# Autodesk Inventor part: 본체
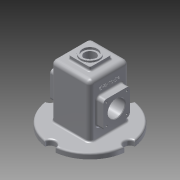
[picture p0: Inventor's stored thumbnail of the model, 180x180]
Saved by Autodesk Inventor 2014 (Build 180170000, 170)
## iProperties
Created: 2018-07
Part Number: 본체
Material: Aluminum 6061
Document SubType Name: Modeling
Designer: kh
Density: 2.71 g/cm^3
Appearance: Aluminum - Flat
Mass: 912.193 g
Surface Area: 1016.11 cm^2
Volume: 336.603 cm^3
Author: kh
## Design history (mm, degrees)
sketch "Sketch1"
  geometry: L1 (-75, 0)-(75, 0); L2 (0, -75)-(0, 75); C1 r 10 at (75, 0); C2 r 10 at (0, 75); C3 r 10 at (-75, 0); C4 r 10 at (0, -75); A1 r 75 centre (0, 0) between (-75, 0) and (75, 0); 1 further point
  constraints: 5 centre point, 5 coincident, 4 end point, 4 point on circle, 1 horizontal, 1 perpendicular
  dimensions: "d0" = 150 diameter of A1; "d2" = 150 distance of L1.start L1.end; "d3" = 150 distance of L2.start L2.end; "d4" = 20 diameter of C1; "d5" = 20 diameter of C2; "d6" = 20 diameter of C3; "d7" = 20 diameter of C4
extrude "Extrusion1" new body sketch "Sketch1" distance "d8" = 10; taper "d9" = 0 deg
extrude "Extrusion2" cut sketch "Sketch1" distance "d10" = 10; taper "d11" = 0 deg
sketch "Sketch2"
  geometry: L1 (-37, -37)-(37, -37); L2 (37, -37)-(37, 37); L3 (37, 37)-(-37, 37); L4 (-37, 37)-(-37, -37); L5 (-37, -37)-(37, 37); L6 (37, -37)-(-37, 37); 1 further point
  constraints: 12 end point, 2 midpoint, 2 parallel, 1 horizontal, 1 perpendicular
  dimensions: "d12" = 74 distance of L3.end L2.end; "d13" = 74 distance of L2.end L1.end
extrude "Extrusion3" join sketch "Sketch2" distance "d14" = 100; taper "d15" = 0 deg
sketch "Sketch3"
  geometry: L1 (-37, -37)-(37, -37) reference; L2 (37, -37)-(37, 37) reference; L3 (37, 37)-(-37, 37) reference; L4 (-37, 37)-(-37, -37) reference; L5 (-20, -20)-(20, -20); L6 (20, -20)-(20, 20); L7 (20, 20)-(-20, 20); L8 (-20, 20)-(-20, -20); L9 (-20, -20)-(20, 20); L10 (20, -20)-(-20, 20); 1 further point
  constraints: 12 end point, 2 midpoint, 2 parallel, 1 horizontal, 1 perpendicular
  dimensions: "d16" = 40 distance of L7.end L6.end; "d17" = 40 distance of L6.end L5.end
extrude "Extrusion4" join sketch "Sketch3" distance "d18" = 7; taper "d19" = 0 deg
sketch "Sketch4"
  geometry: L1 (-20, -20)-(20, -20) reference; L2 (20, -20)-(20, 20) reference; L3 (20, 20)-(-20, 20) reference; L4 (-20, 20)-(-20, -20) reference; C1 r 17.5 at (0, 0); 1 further point
  constraints: 1 centre point, 1 coincident
  dimensions: "d20" = 35 diameter of C1
extrude "Extrusion5" join sketch "Sketch4" distance "d21" = 3; taper "d22" = 0 deg
sketch "Sketch5"
  geometry: L1 (65, 10)-(65, 0) reference; L2 (65, 0)-(-65, 0) reference; L3 (-65, 0)-(-65, 10) reference; L4 (-65, 10)-(-37, 10) reference; L5 (-37, 10)-(-37, 110) reference; L6 (-37, 110)-(-20, 110) reference; L7 (-20, 110)-(-20, 117) reference; L8 (-20, 117)-(-17.5, 117) reference; L9 (-17.5, 117)-(-17.5, 120) reference; L10 (-17.5, 120)-(17.5, 120) reference; L11 (17.5, 120)-(17.5, 117) reference; L12 (17.5, 117)-(20, 117) reference; L13 (20, 117)-(20, 110) reference; L14 (20, 110)-(37, 110) reference; L15 (37, 110)-(37, 10) reference; L16 (37, 10)-(65, 10) reference; L17 (-32, 105)-(32, 105); L18 (32, 105)-(32, 0); L19 (32, 0)-(-32, 0); L20 (-32, 0)-(-32, 105)
  constraints: 8 end point, 2 parallel, 1 horizontal, 1 perpendicular, 1 point on line
  dimensions: "d26" = 64 distance of L18.end L19.end; "d27" = 5 distance between parallel lines of L15 L18; "d29" = 5 distance between parallel lines of L17 L6
extrude "Extrusion6" cut sketch "Sketch5" stored distance "d30" = 64; taper "d31" = 0 deg
sketch "Sketch7"
  geometry: L1 (70, 62)-(20, 62); L2 (20, 62)-(20, 12); L3 (20, 12)-(70, 12); L4 (70, 12)-(70, 62); L5 (70, 37)-(20, 37); L6 (45, 12)-(45, 62); 2 further points
  constraints: 12 end point, 5 midpoint, 2 parallel, 1 horizontal, 1 horizontal alignment, 1 perpendicular
  dimensions: "d33" = 50 distance of L2.end L3.end; "d34" = 50 distance of L1.end L2.end; "d35" = 55 distance from line of point (-10, 37) L6
extrude "Extrusion7" join sketch "Sketch7" distance "d36" = 13; taper "d37" = 0 deg
mirror "Mirror1"
sketch "Sketch8"
  geometry: L1 (65, 10)-(65, 0) reference; L2 (65, 0)-(32, 0) reference; L3 (32, 0)-(32, 105) reference; L4 (32, 105)-(-32, 105) reference; L5 (-32, 105)-(-32, 0) reference; L6 (-32, 0)-(-65, 0) reference; L7 (-65, 0)-(-65, 10) reference; L8 (-65, 10)-(-37, 10) reference; L9 (-37, 10)-(-37, 30) reference; L10 (-37, 30)-(-50, 30) reference; L11 (-50, 30)-(-50, 80) reference; L12 (-50, 80)-(-37, 80) reference; L13 (-37, 80)-(-37, 110) reference; L14 (-37, 110)-(-20, 110) reference; L15 (-20, 110)-(-20, 117) reference; L16 (-20, 117)-(-17.5, 117) reference; L17 (-17.5, 117)-(-17.5, 120) reference; L18 (-17.5, 120)-(17.5, 120) reference; L19 (17.5, 120)-(17.5, 117) reference; L20 (17.5, 117)-(20, 117) reference; L21 (20, 117)-(20, 110) reference; L22 (20, 110)-(37, 110) reference; L23 (37, 110)-(37, 80) reference; L24 (37, 80)-(50, 80) reference; L25 (50, 80)-(50, 30) reference; L26 (50, 30)-(37, 30) reference; L27 (37, 30)-(37, 10) reference; L28 (37, 10)-(65, 10) reference; L29 (-32, 55)-(32, 55); L30 (-32, 30)-(-25, 32.548); L31 (-25, 32.548)-(-25, 55); L32 (-32, 30)-(-32, 55); 1 further point
  constraints: 8 end point, 4 point on line, 2 perpendicular, 1 collinear
  dimensions: "d38" = 55 vertical distance of point (0, 0) L29.end; "d39" = 7 distance between parallel lines of L32 L31; "d40" = 110 deg angle of L5 L30; "d41" = 50 diameter of L30.start L29
revolve "Revolution1" sketch "Sketch8" stored, may be unused: angle "d42" = 90 deg
mirror "Mirror2"
sketch "Sketch9"
  geometry: C1 r 16 at (25, 25); 1 further point
  constraints: 1 centre point, 1 horizontal alignment
  dimensions: "d43" = 32 diameter of C1; "d44" = 55 distance of C1.centre point (80, 25)
extrude "Extrusion8" cut sketch "Sketch9" stored distance "d45" = 13; taper "d46" = 0 deg
sketch "Sketch10"
  geometry: C1 r 17.5 at (0, 0) reference; 1 further point
hole "Hole1" sketch "Sketch10" at (0, 0) diameter "d47" = 21; stored, may be unused: countersink angle "d51" = 90 deg, drill point angle "d53" = 0 deg; dims "d48" = 6, "d49" = 28, "d50" = 4, "d52" = 8
fillet "Fillet1" dims "d54" = 8
fillet "Fillet2" dims "d55" = 3
fillet "Fillet5" dims "d58" = 6
fillet "Fillet6" dims "d59" = 6
sketch "Sketch11"
  geometry: L1 (50, 38)-(50, 0) reference; L2 (44, -6)-(6, -6) reference; L3 (0, 0)-(0, 38) reference; L4 (6, 44)-(44, 44) reference; L5 (70, -32.807)-(70, 70.807) reference; L6 (73, 74.902)-(80, 74.902) reference; L7 (80, 74.902)-(80, -36.902) reference; L8 (80, -36.902)-(73, -36.902) reference; C1 r 16 at (25, 19) reference; A1 r 6 centre (44, 38) between (50, 38) and (44, 44) reference; A2 r 6 centre (44, 0) between (44, -6) and (50, 0) reference; A3 r 6 centre (6, 0) between (0, 0) and (6, -6) reference; A4 r 6 centre (6, 38) between (6, 44) and (0, 38) reference; 1 further point
  constraints: 2 other
hole "Hole2" sketch "Sketch11" at (6, 0), (44, 0), (44, 38), (6, 38) diameter "d60" = 3.242; stored, may be unused: countersink angle "d64" = 90 deg, drill point angle "d66" = 118 deg; dims "d61" = 8, "d62" = 28, "d63" = 4, "d65" = 10
sketch "Sketch12"
  geometry: L1 (26, 62)-(64, 62) reference; L2 (70, 56)-(70, 18) reference; L3 (64, 12)-(26, 12) reference; L4 (20, 18)-(20, 56) reference; L5 (0, 88.807)-(0, -14.807) reference; L6 (-3, -18.902)-(-10, -18.902) reference; L7 (-10, -18.902)-(-10, 92.902) reference; L8 (-10, 92.902)-(-3, 92.902) reference; C1 r 16 at (45, 37) reference; A1 r 6 centre (26, 56) between (26, 62) and (20, 56) reference; A2 r 6 centre (64, 56) between (70, 56) and (64, 62) reference; A3 r 6 centre (64, 18) between (64, 12) and (70, 18) reference; A4 r 6 centre (26, 18) between (20, 18) and (26, 12) reference; 1 further point
  constraints: 2 other
hole "Hole3" sketch "Sketch12" at (64, 56), (26, 56), (26, 18), (64, 18) diameter "d67" = 3.242; stored, may be unused: countersink angle "d71" = 90 deg, drill point angle "d73" = 118 deg; dims "d68" = 8, "d69" = 28, "d70" = 4, "d72" = 10
fillet "Fillet7" dims "d74" = 3
chamfer "Chamfer1" distance "d76" = 1; stored, may be unused: second distance "d77" = 2, angle "d78" = 45 deg
fillet "Fillet9" dims "d79" = 3
fillet "Fillet10" dims "d84" = 8
fillet "Fillet11" dims "d85" = 3
sketch "Sketch14"
  geometry: L1 (-4.176, -5.921)-(-4.176, 63.921); L2 (-4.176, 63.921)-(28.176, 63.921); L3 (28.176, 63.921)-(28.176, -5.921); L4 (28.176, -5.921)-(-4.176, -5.921); L5 (12, -5.921)-(12, 63.921); L6 (-4.176, 29)-(28.176, 29); L7 (89, 66)-(0, 66) reference; L8 (-18, 46.5)-(-18, 11.5) reference; 1 further point
  constraints: 4 end point, 4 midpoint, 2 other
  dimensions: "d86" = 37 distance between parallel lines of L7 L6; "d87" = 30 distance between parallel lines of L8 L5
emboss "Emboss2" sketch "Sketch14" dims "d88" = 0.5, "d89" = 0
chamfer "Chamfer2" distance "d90" = 1; stored, may be unused: second distance "d91" = 2, angle "d92" = 45 deg
fillet "Fillet13" dims "d94" = 3
fillet "Fillet14" dims "d95" = 3
body "Solid1"
node "Projected Loop1"
node "Projected Loop2"
node "Project Cut Edges1"
node "Project Cut Edges3"
node "Project Cut Edges4"
node "Project Cut Edges5"
node "Project Cut Edges6"
